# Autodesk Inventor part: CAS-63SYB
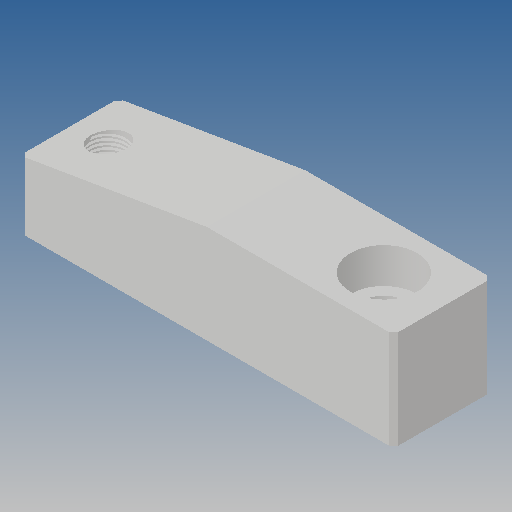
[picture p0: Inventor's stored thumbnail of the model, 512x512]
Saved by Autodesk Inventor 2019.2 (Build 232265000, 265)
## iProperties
Created: 2009-09
Part Number: CAS-63SYB
Material: Ogólny
Document SubType Name: Modeling
Designer: CADENGINEERING4
Density: 1 g/cm^3
Appearance: Domyślna
Author: CADENGINEERING4
Revision Number: 1LAST_VERSION
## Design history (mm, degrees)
feature "Baza1"
node "Bryła1"
